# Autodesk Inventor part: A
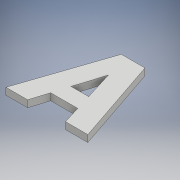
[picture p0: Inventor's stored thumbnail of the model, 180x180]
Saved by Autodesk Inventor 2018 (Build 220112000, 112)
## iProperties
Created: 2020-11
Part Number: A
Material: Genérico
Document SubType Name: Modeling
Designer: ULISES
Density: 1 g/cm^3
Appearance: Valor por defecto
Author: ULISES
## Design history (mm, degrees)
sketch "Boceto1"
  geometry: L1 (0, 0)-(40, 0); L2 (40, 0)-(40, 40); L3 (40, 40)-(0, 40); L4 (0, 40)-(0, 0); L5 (2.19, 39.488)-(40.181, 39.488); L6 (40.181, 39.488)-(40.181, -0.512); L7 (40.181, -0.512)-(2.19, -0.512); L8 (2.19, -0.512)-(2.19, 39.488)
  constraints: 8 end point, 2 parallel, 1 horizontal, 1 perpendicular, 2 other
  dimensions: "d0" = 40 distance of L3.end L1.start; "d1" = 40 distance of L1.start L1.end
extrude "Extrusión1" new body sketch "Boceto1" distance "d2" = 3.2; taper "d3" = 0 deg
node "Sólido1"
